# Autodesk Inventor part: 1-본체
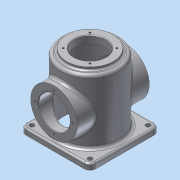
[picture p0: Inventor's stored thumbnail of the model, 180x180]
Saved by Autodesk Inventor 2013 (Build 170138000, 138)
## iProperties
Created: 2015-10
Part Number: 1-본체
Material: 알루미늄 6061
Document SubType Name: Modeling
Designer: Administrator
Mass: 987.678 g
Surface Area: 1044.24 cm^2
Volume: 364.457 cm^3
Density: 2.71 g/cm^3
Author: Administrator
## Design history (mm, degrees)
sketch "스케치1"
  geometry: L1 (-60, 60)-(60, 60); L2 (60, 60)-(60, -60); L3 (60, -60)-(-60, -60); L4 (-60, -60)-(-60, 60); 3 further points
  constraints: 8 end point, 2 midpoint, 2 parallel, 1 horizontal, 1 horizontal alignment, 1 perpendicular, 1 vertical alignment
  dimensions: "d0" = 120 distance of L1.start L1.end; "d2" = 120 distance of L1.end L2.end
extrude "돌출1" new body sketch "스케치1" distance "d3" = 10; taper "d4" = 0 deg
sketch "스케치3"
  geometry: C1 r 50 at (0, 0); 1 further point
  constraints: 1 centre point, 1 coincident
  dimensions: "d5" = 100 diameter of C1
extrude "돌출2" join sketch "스케치3" distance "d7" = 120; taper "d8" = 0 deg
sketch "스케치6"
  geometry: C1 r 50 at (0, 0) reference; C2 r 40 at (0, 0); 1 further point
  constraints: 1 centre point, 1 coincident
  dimensions: "d9" = 80 diameter of C2
extrude "돌출3" join sketch "스케치6" distance "d11" = 5; taper "d12" = 0 deg
node "작업 평면1"
sketch "스케치7"
  geometry: L1 (50, 120)-(-50, 120) reference; L2 (-50, 10)-(50, 10) reference; L3 (60, 0)-(-60, 0) reference; L4 (60, 0)-(60, 10) reference; L5 (-60, 10)-(60, 10) reference; L6 (-60, 0)-(-60, 10) reference; L7 (-50, 10)-(-50, 120) reference; L8 (50, 10)-(50, 120) reference; C1 r 40 at (0, 60); 2 further points
  constraints: 1 centre point, 1 midpoint, 1 vertical alignment
  dimensions: "d14" = 80 diameter of C1; "d16" = 60 distance of point (0, 0) C1.centre
extrude "돌출4" join sketch "스케치7" distance "d17" = 124; taper "d18" = 0 deg
hole "구멍1" diameter "d21" = 54; stored, may be unused: countersink angle "d25" = 90 deg, drill point angle "d27" = 0 deg; dims "d19" = 10, "d20" = 10, "d22" = 6, "d23" = 4, "d24" = 2, "d26" = 8
sketch "스케치8" dims "d28" = 65
  geometry: C1 r 27 at (0, 0) reference; C2 r 40 at (0, 0) reference; 3 further points
  constraints: 2 vertical alignment, 1 coincident, 2 other
hole "구멍2" sketch "스케치8" at (0, -32.5) diameter "d30" = 3.242; stored, may be unused: countersink angle "d34" = 90 deg, drill point angle "d36" = 118 deg; dims "d31" = 8, "d32" = 4, "d33" = 2, "d35" = 10
node "작업 평면2"
node "작업 평면3"
sketch "스케치9"
  geometry: L1 (-3.602, 45.113)-(-3.602, 94.887); L2 (-3.602, 94.887)-(3.602, 94.887); L3 (3.602, 94.887)-(3.602, 45.113); L4 (3.602, 45.113)-(-3.602, 45.113); L5 (40, 125)-(-40, 125) reference; L6 (50, 120)-(-50, 120) reference; L7 (60, 0)-(-60, 0) reference; 5 further points
  constraints: 3 midpoint, 2 vertical alignment, 1 horizontal alignment, 2 other
  dimensions: "d42" = 70 distance from line of point (0, 70) L7
feature "엠보싱1" sketch "스케치9" dims "d0" = 120, "d2" = 120, "d43" = 0.5, "d44" = 0
hole "구멍3" diameter "d47" = 54; stored, may be unused: countersink angle "d51" = 90 deg, drill point angle "d53" = 0 deg; dims "d45" = 10, "d46" = 10, "d48" = 8, "d49" = 4, "d50" = 2, "d52" = 13
sketch "스케치10"
  geometry: C1 r 45 at (0, 0); 1 further point
  constraints: 1 centre point, 1 coincident
  dimensions: "d54" = 90 diameter of C1
extrude "돌출5" cut sketch "스케치10" distance "d56" = 112; taper "d57" = 0 deg
sketch "스케치11"
  geometry: A1 r 32.5 centre (0, 0) between (-22.981, -22.981) and (-22.981, 22.981); 3 further points
  constraints: 4 point on circle, 2 horizontal alignment, 2 vertical alignment, 1 centre point, 1 coincident
  dimensions: "d58" = 65 diameter of A1; "d60" = 90 deg dimension on point (0, 0) A1.end A1.start
hole "구멍4" sketch "스케치11" at (-22.981, -22.981), (-22.981, 22.981), (22.981, 22.981), (22.981, -22.981) diameter "d62" = 3.242; stored, may be unused: countersink angle "d66" = 90 deg, drill point angle "d68" = 118 deg; dims "d63" = 8, "d64" = 4, "d65" = 2, "d67" = 10
sketch "스케치12"
  geometry: 5 further points
  constraints: 2 horizontal alignment, 2 vertical alignment
  dimensions: "d69" = 50 horizontal distance of point (-50, -50) point (0, 0); "d70" = 100 distance of point (50, 50) point (-50, 50); "d71" = 100 distance of point (-50, -50) point (-50, 50); "d72" = 50 horizontal distance of point (-50, 50) point (0, 0)
hole "구멍5" sketch "스케치12" at (-50, -50), (-50, 50), (50, 50), (50, -50) diameter "d73" = 8; stored, may be unused: countersink angle "d77" = 90 deg, drill point angle "d79" = 0 deg; dims "d74" = 8, "d75" = 4, "d76" = 2, "d78" = 10
fillet "모깎기1" dims "d80" = 10
fillet "모깎기2" dims "d81" = 3
chamfer "모따기1" distance "d82" = 1; stored, may be unused: second distance "d83" = 2, angle "d84" = 45 deg
fillet "모깎기3" dims "d85" = 5
fillet "모깎기4" dims "d86" = 5
fillet "모깎기5" dims "d87" = 3
fillet "모깎기6" dims "d88" = 3
node "솔리드1"
pattern_circular "원형 패턴1" dims angle "d38" = 360 deg
mirror "대칭1"
node "투영된 루프1"
node "투영된 루프2"
node "투영된 루프3"
other parameters: "d13" = 62
